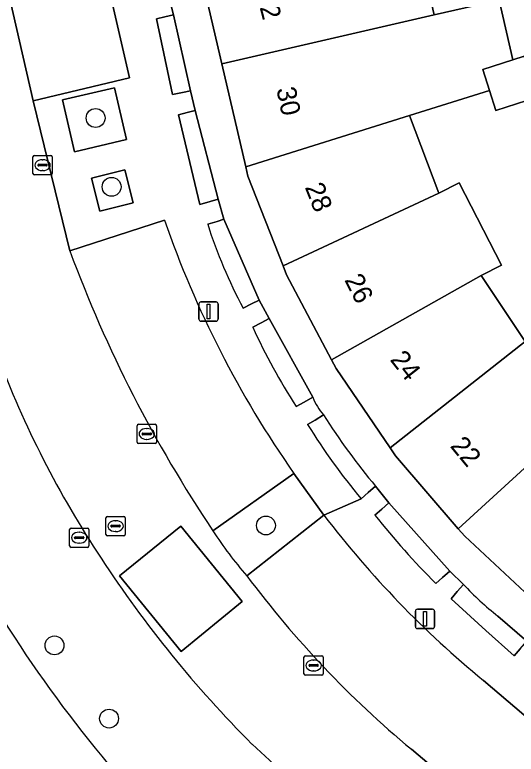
# Model space of a CAD drawing. Extents: x 156412 to 157779, y 382335 to 383768.
# Drawn here: x 157024.9 to 157050.87, y 382894.98 to 382933.25 of the extents above; entities that cross this region are included whole.
import ezdxf

# ---------------------------------------------------------------- set-up
doc = ezdxf.new("R2010")
doc.units = 0
for name, color, linetype in [('IMGEO_Berm_groen', 7, 'Continuous'), ('IMGEO_Boom', 7, 'Continuous'), ('IMGEO_Erf', 7, 'Continuous'), ('IMGEO_Groenvoorziening', 7, 'Continuous'), ('IMGEO_Haag', 7, 'Continuous'), ('IMGEO_Kolk', 7, 'Continuous'), ('IMGEO_Lichtmast', 7, 'Continuous'), ('IMGEO_OVBaan_gesloten', 7, 'Continuous'), ('IMGEO_Pand', 7, 'Continuous'), ('IMGEO_Pand_nummerreeks', 7, 'Continuous'), ('IMGEO_Parkeervlak_open', 7, 'Continuous'), ('IMGEO_Rijbaan_lokaal_gesloten', 7, 'Continuous'), ('IMGEO_Rijbaan_lokaal_open', 7, 'Continuous'), ('IMGEO_Rioolput', 7, 'Continuous'), ('IMGEO_Voetpad_open', 7, 'Continuous')]:
    doc.layers.add(name, color=color, linetype=linetype)

msp = doc.modelspace()

# ---------------------------------------------------------------- linework, layer by layer
at = {"layer": 'IMGEO_Berm_groen'}
for points in [[(157040.904, 382907.361), (157039.349, 382909.517), (157035.16, 382906.543)], [(157036.914, 382904.221), (157040.904, 382907.361)], [(157033.831, 382890.025), (157036.951, 382886.961), (157041.226, 382891.768), (157037.183, 382895.505)]]:
    msp.add_lwpolyline(points, dxfattribs=at)
for centre, radius, start, end in [((157073.619, 382934.389), 53.056, 200.6417, 213.4778), ((157050.99, 382916.677), 18.796, 212.6271, 221.5065), ((157080.152, 382938.419), 60.729, 213.2488, 224.96314), ((157080.911, 382937.438), 66.817, 210.18195, 225.20205), ((157072.354, 382932.861), 64.885, 210.9363, 229.54412)]:
    msp.add_arc(centre, radius, start, end, dxfattribs=at)
at = {"layer": 'IMGEO_Boom'}
for centre in [(157029.082, 382927.908), (157029.912, 382924.346), (157037.906, 382906.82), (157026.953, 382900.613), (157029.779, 382896.825)]:
    msp.add_circle(centre, 0.489, dxfattribs=at)
at = {"layer": 'IMGEO_Erf'}
for points in [[(157033.388, 382968.999), (157025.312, 382967.098), (157026.438, 382961.994), (157026.708, 382960.971), (157027.168, 382959.149), (157027.386, 382958.094), (157028.3, 382954.14), (157028.516, 382953.106), (157029.418, 382949.184), (157029.615, 382948.171), (157030.556, 382944.265), (157030.788, 382943.23), (157031.737, 382939.296), (157031.943, 382938.26), (157032.864, 382934.281), (157033.111, 382933.246), (157034.001, 382929.316), (157034.235, 382928.299), (157035.422, 382923.7), (157035.726, 382922.668), (157037.556, 382918.474), (157038.079, 382917.533), (157040.336, 382913.453)], [(157045.462, 382938.216), (157046.61, 382933.247), (157049.976, 382934.025), (157050.695, 382930.914), (157051.275, 382931.1), (157053.417, 382931.79), (157052.698, 382938.729)], [(157082.934, 382876.466), (157079.046, 382879.765), (157075.157, 382883.065), (157071.268, 382886.365), (157067.379, 382889.664), (157063.49, 382892.964), (157059.602, 382896.263), (157055.713, 382899.563), (157051.839, 382902.879), (157048.2, 382906.264), (157047.866, 382906.651), (157044.615, 382910.42), (157044.337, 382910.83), (157041.542, 382914.944), (157041.305, 382915.392), (157038.976, 382919.795), (157038.795, 382920.253), (157036.968, 382924.901), (157036.857, 382925.379), (157035.623, 382930.709), (157034.472, 382935.677)], [(157051.956, 382928.99), (157049.811, 382928.301), (157049.482, 382929.324), (157045.342, 382928.03), (157046.862, 382924.018), (157047.911, 382924.558), (157050.105, 382920.297), (157049.056, 382919.757), (157051.324, 382916.339)], [(157043.586, 382908.852), (157044.265, 382907.992), (157047.422, 382904.462), (157048.129, 382903.772)], [(157049.923, 382902.132), (157051.414, 382900.824), (157052.174, 382900.111), (157055.262, 382897.527), (157056.106, 382896.836), (157059.141, 382894.249), (157059.952, 382893.555), (157063.086, 382890.937), (157063.917, 382890.211), (157066.966, 382887.621), (157067.779, 382886.911), (157070.828, 382884.357), (157071.619, 382883.687), (157074.699, 382881.06), (157075.52, 382880.404), (157078.608, 382877.784), (157079.414, 382877.065), (157082.481, 382874.48)]]:
    msp.add_lwpolyline(points, dxfattribs=at)
for centre, radius, start, end in [((157042.905, 382914.392), 2.735, 200.0704, 222.6108), ((157069.198, 382930.389), 33.464, 212.2344, 220.0602), ((157058.267, 382913.061), 13.75, 222.4971, 232.6384)]:
    msp.add_arc(centre, radius, start, end, dxfattribs=at)
at = {"layer": 'IMGEO_Groenvoorziening'}
for points in [[(157034.001, 382929.316), (157033.111, 382933.246), (157032.669, 382933.143), (157032.232, 382933.042), (157033.067, 382929.127), (157033.577, 382929.23)], [(157030.679, 382926.79), (157030.054, 382929.478), (157027.363, 382928.852), (157027.988, 382926.164)], [(157035.422, 382923.7), (157034.235, 382928.299), (157033.818, 382928.192), (157033.382, 382928.08), (157034.488, 382923.434), (157035.022, 382923.586)], [(157031.031, 382923.521), (157030.604, 382925.227), (157028.876, 382924.795), (157029.303, 382923.089)]]:
    msp.add_lwpolyline(points, close=True, dxfattribs=at)
for points in [[(157036.723, 382918.071), (157037.163, 382918.284), (157037.556, 382918.474), (157035.726, 382922.668), (157035.374, 382922.558), (157034.891, 382922.406)], [(157039.476, 382912.977), (157039.881, 382913.201), (157040.336, 382913.453), (157038.079, 382917.533), (157037.651, 382917.304), (157037.228, 382917.079)], [(157040.892, 382912.54), (157040.454, 382912.274), (157040.065, 382912.038)], [(157042.838, 382908.2), (157043.203, 382908.518), (157043.586, 382908.852)], [(157046.699, 382903.818), (157047.054, 382904.134), (157047.422, 382904.462), (157044.265, 382907.992), (157043.908, 382907.672), (157043.553, 382907.354)], [(157048.129, 382903.772), (157047.813, 382903.396), (157047.504, 382903.029), (157049.299, 382901.379), (157050.762, 382900.082), (157051.069, 382900.431), (157051.414, 382900.824), (157049.923, 382902.132)]]:
    msp.add_lwpolyline(points, dxfattribs=at)
for centre, radius, start, end in [((157059.514, 382930.257), 25.845, 197.6853, 208.1332), ((157065.241, 382929.764), 30.752, 204.362, 213.0857), ((157069.198, 382930.389), 33.464, 212.2344, 220.0602), ((157068.389, 382929.582), 33.318, 211.7738, 219.9233), ((157075.858, 382932.929), 41.203, 218.3671, 224.9522), ((157058.267, 382913.061), 13.75, 222.4971, 232.6384)]:
    msp.add_arc(centre, radius, start, end, dxfattribs=at)
at = {"layer": 'IMGEO_Haag'}
for points in [[(157034.001, 382929.316), (157033.111, 382933.246), (157032.669, 382933.143), (157032.232, 382933.042), (157033.067, 382929.127), (157033.577, 382929.23)], [(157035.422, 382923.7), (157034.235, 382928.299), (157033.818, 382928.192), (157033.382, 382928.08), (157034.488, 382923.434), (157035.022, 382923.586)]]:
    msp.add_lwpolyline(points, close=True, dxfattribs=at)
for points in [[(157036.723, 382918.071), (157037.163, 382918.284), (157037.556, 382918.474), (157035.726, 382922.668), (157035.374, 382922.558), (157034.891, 382922.406)], [(157039.476, 382912.977), (157039.881, 382913.201), (157040.336, 382913.453), (157038.079, 382917.533), (157037.651, 382917.304), (157037.228, 382917.079)], [(157040.892, 382912.54), (157040.454, 382912.274), (157040.065, 382912.038)], [(157042.838, 382908.2), (157043.203, 382908.518), (157043.586, 382908.852)], [(157046.699, 382903.818), (157047.054, 382904.134), (157047.422, 382904.462), (157044.265, 382907.992), (157043.908, 382907.672), (157043.553, 382907.354)], [(157048.129, 382903.772), (157047.813, 382903.396), (157047.504, 382903.029), (157049.299, 382901.379), (157050.762, 382900.082), (157051.069, 382900.431), (157051.414, 382900.824), (157049.923, 382902.132)]]:
    msp.add_lwpolyline(points, dxfattribs=at)
for centre, radius, start, end in [((157059.514, 382930.257), 25.845, 197.6853, 208.1332), ((157065.241, 382929.764), 30.752, 204.362, 213.0857), ((157069.198, 382930.389), 33.464, 212.2344, 220.0602), ((157068.389, 382929.582), 33.318, 211.7738, 219.9233), ((157075.858, 382932.929), 41.203, 218.3671, 224.9522), ((157058.267, 382913.061), 13.75, 222.4971, 232.6384)]:
    msp.add_arc(centre, radius, start, end, dxfattribs=at)
at = {"layer": 'IMGEO_Kolk'}
for p, q in [((157025.835, 382925.042), (157025.835, 382925.894)), ((157025.91, 382925.968), (157026.762, 382925.968)), ((157026.323, 382925.748), (157026.348, 382925.748)), ((157026.836, 382925.894), (157026.836, 382925.042)), ((157026.094, 382925.462), (157026.094, 382925.474)), ((157026.532, 382925.425), (157026.134, 382925.425)), ((157026.137, 382925.511), (157026.535, 382925.511)), ((157026.578, 382925.474), (157026.578, 382925.462)), ((157026.762, 382924.968), (157025.91, 382924.968)), ((157026.346, 382925.188), (157026.321, 382925.188)), ((157031.232, 382911.131), (157031.232, 382911.983)), ((157031.307, 382912.057), (157032.159, 382912.057)), ((157032.233, 382911.983), (157032.233, 382911.131)), ((157031.491, 382911.551), (157031.491, 382911.563)), ((157031.534, 382911.6), (157031.932, 382911.6)), ((157031.72, 382911.837), (157031.745, 382911.837)), ((157031.975, 382911.563), (157031.975, 382911.551)), ((157031.929, 382911.514), (157031.531, 382911.514)), ((157031.743, 382911.277), (157031.718, 382911.277)), ((157032.159, 382911.057), (157031.307, 382911.057)), ((157039.95, 382900.075), (157040.802, 382900.075)), ((157039.875, 382899.149), (157039.875, 382900.001)), ((157040.363, 382899.855), (157040.388, 382899.855)), ((157040.876, 382900.001), (157040.876, 382899.149)), ((157040.134, 382899.569), (157040.134, 382899.581)), ((157040.572, 382899.532), (157040.174, 382899.532)), ((157040.177, 382899.618), (157040.575, 382899.618)), ((157040.386, 382899.295), (157040.361, 382899.295)), ((157040.618, 382899.581), (157040.618, 382899.569)), ((157040.802, 382899.075), (157039.95, 382899.075))]:
    msp.add_line(p, q, dxfattribs=at)
for points in [[(157025.835, 382925.042), (157025.835, 382925.894)], [(157025.91, 382925.968), (157026.762, 382925.968)], [(157026.836, 382925.894), (157026.836, 382925.042)], [(157026.762, 382924.968), (157025.91, 382924.968)], [(157031.232, 382911.131), (157031.232, 382911.983)], [(157031.307, 382912.057), (157032.159, 382912.057)], [(157032.233, 382911.983), (157032.233, 382911.131)], [(157032.159, 382911.057), (157031.307, 382911.057)], [(157039.95, 382900.075), (157040.802, 382900.075)], [(157039.875, 382899.149), (157039.875, 382900.001)], [(157040.876, 382900.001), (157040.876, 382899.149)], [(157040.802, 382899.075), (157039.95, 382899.075)]]:
    msp.add_lwpolyline(points, dxfattribs=at)
for centre, radius, start, end in [((157025.912, 382925.892), 0.0765, 91.552, 178.448), ((157025.912, 382925.892), 0.0765, 91.552, 178.448), ((157026.76, 382925.892), 0.0765, 1.552, 88.448), ((157026.76, 382925.892), 0.0765, 1.552, 88.448), ((157026.134, 382925.471), 0.0403, 85.8775, 175.7526), ((157026.131, 382925.461), 0.0366, 178.938, 274.7102), ((157026.535, 382925.468), 0.043, 264.8664, 352.4533), ((157026.539, 382925.473), 0.0386, 1.7309, 96.639), ((157025.912, 382925.044), 0.0765, 181.552, 268.448), ((157025.912, 382925.044), 0.0765, 181.552, 268.448), ((157026.76, 382925.044), 0.0765, 271.552, 358.448), ((157026.76, 382925.044), 0.0765, 271.552, 358.448), ((157031.309, 382911.981), 0.0765, 91.552, 178.448), ((157031.309, 382911.981), 0.0765, 91.552, 178.448), ((157032.157, 382911.981), 0.0765, 1.552, 88.448), ((157032.157, 382911.981), 0.0765, 1.552, 88.448), ((157031.531, 382911.56), 0.0403, 85.8775, 175.7526), ((157031.528, 382911.55), 0.0366, 178.938, 274.7102), ((157031.932, 382911.557), 0.043, 264.8664, 352.4533), ((157031.936, 382911.562), 0.0386, 1.7309, 96.639), ((157031.309, 382911.133), 0.0765, 181.552, 268.448), ((157031.309, 382911.133), 0.0765, 181.552, 268.448), ((157032.157, 382911.133), 0.0765, 271.552, 358.448), ((157032.157, 382911.133), 0.0765, 271.552, 358.448), ((157039.952, 382899.999), 0.0765, 91.552, 178.448), ((157039.952, 382899.999), 0.0765, 91.552, 178.448), ((157040.8, 382899.999), 0.0765, 1.552, 88.448), ((157040.8, 382899.999), 0.0765, 1.552, 88.448), ((157040.174, 382899.578), 0.0403, 85.8775, 175.7526), ((157040.171, 382899.568), 0.0366, 178.938, 274.7102), ((157040.575, 382899.575), 0.043, 264.8664, 352.4533), ((157040.579, 382899.58), 0.0386, 1.7309, 96.639), ((157039.952, 382899.151), 0.0765, 181.552, 268.448), ((157039.952, 382899.151), 0.0765, 181.552, 268.448), ((157040.8, 382899.151), 0.0765, 271.552, 358.448), ((157040.8, 382899.151), 0.0765, 271.552, 358.448)]:
    msp.add_arc(centre, radius, start, end, dxfattribs=at)
for centre, major_axis, ratio, start_param, end_param in [((157026.322, 382925.468), (-0.387, 0.002), 0.722429, 4.712389, 7.853982), ((157026.347, 382925.468), (-0.39, 0.002), 0.717154, 1.570796, 4.712389), ((157031.719, 382911.557), (-0.387, 0.002), 0.722429, 4.712389, 7.853982), ((157031.744, 382911.557), (-0.39, 0.002), 0.717154, 1.570796, 4.712389), ((157040.362, 382899.575), (-0.387, 0.002), 0.722429, 4.712389, 7.853982), ((157040.387, 382899.575), (-0.39, 0.002), 0.717154, 1.570796, 4.712389)]:
    msp.add_ellipse(centre, major_axis=major_axis, ratio=ratio, start_param=start_param, end_param=end_param, dxfattribs=at)
at = {"layer": 'IMGEO_Lichtmast'}
for p, q in [((157034.434, 382917.493), (157034.434, 382918.293)), ((157034.434, 382918.293), (157034.434, 382917.493)), ((157034.534, 382918.393), (157035.324, 382918.393)), ((157035.324, 382918.393), (157034.534, 382918.393)), ((157035.424, 382918.293), (157035.424, 382917.493)), ((157035.424, 382917.493), (157035.424, 382918.293)), ((157035.324, 382917.393), (157034.534, 382917.393)), ((157034.534, 382917.393), (157035.324, 382917.393)), ((157045.646, 382901.585), (157045.646, 382902.385)), ((157045.646, 382902.385), (157045.646, 382901.585)), ((157045.746, 382902.485), (157046.536, 382902.485)), ((157046.536, 382902.485), (157045.746, 382902.485)), ((157046.636, 382902.385), (157046.636, 382901.585)), ((157046.636, 382901.585), (157046.636, 382902.385)), ((157046.536, 382901.485), (157045.746, 382901.485)), ((157045.746, 382901.485), (157046.536, 382901.485))]:
    msp.add_line(p, q, dxfattribs=at)
for points in [[(157034.854, 382918.268), (157035.004, 382918.268), (157035.004, 382917.518), (157034.854, 382917.518), (157034.854, 382918.268)], [(157046.066, 382902.36), (157046.216, 382902.36), (157046.216, 382901.61), (157046.066, 382901.61), (157046.066, 382902.36)]]:
    msp.add_lwpolyline(points, dxfattribs=at)
for centre, start, end in [((157034.534, 382918.293), 90, 180), ((157034.534, 382918.293), 90, 180), ((157035.324, 382918.293), 0, 90), ((157035.324, 382918.293), 360, 90), ((157034.534, 382917.493), 180, 270), ((157034.534, 382917.493), 180, 270), ((157035.324, 382917.493), 270, 0), ((157035.324, 382917.493), 270, 0), ((157045.746, 382902.385), 90, 180), ((157045.746, 382902.385), 90, 180), ((157046.536, 382902.385), 0, 90), ((157046.536, 382902.385), 360, 90), ((157045.746, 382901.585), 180, 270), ((157045.746, 382901.585), 180, 270), ((157046.536, 382901.585), 270, 0), ((157046.536, 382901.585), 270, 0)]:
    msp.add_arc(centre, 0.1, start, end, dxfattribs=at)
at = {"layer": 'IMGEO_OVBaan_gesloten'}
for centre, radius, start, end in [((157080.911, 382937.438), 66.817, 210.18195, 225.20205), ((157072.354, 382932.861), 64.885, 210.9363, 229.54412)]:
    msp.add_arc(centre, radius, start, end, dxfattribs=at)
at = {"layer": 'IMGEO_Pand'}
for points in [[(157046.61, 382933.247), (157045.462, 382938.216), (157034.472, 382935.677), (157035.623, 382930.709)], [(157049.482, 382929.324), (157049.133, 382930.411), (157050.695, 382930.914), (157049.976, 382934.025), (157046.61, 382933.247), (157035.623, 382930.709), (157036.857, 382925.379), (157045.342, 382928.03)], [(157051.275, 382931.1), (157050.695, 382930.914), (157049.133, 382930.411), (157049.482, 382929.324), (157049.811, 382928.301), (157051.956, 382928.99)], [(157046.862, 382924.018), (157045.342, 382928.03), (157036.857, 382925.379), (157036.968, 382924.901), (157038.795, 382920.253)], [(157046.862, 382924.018), (157038.795, 382920.253), (157038.976, 382919.795), (157041.305, 382915.392), (157049.056, 382919.757), (157050.105, 382920.297), (157047.911, 382924.558)], [(157041.305, 382915.392), (157041.542, 382914.944), (157044.337, 382910.83), (157051.324, 382916.339), (157049.056, 382919.757)], [(157055.327, 382913.457), (157056.229, 382914.217), (157053.225, 382917.778), (157051.324, 382916.339), (157044.337, 382910.83), (157044.615, 382910.42), (157047.866, 382906.651)], [(157051.839, 382902.879), (157058.192, 382910.708), (157055.327, 382913.457), (157047.866, 382906.651), (157048.2, 382906.264)]]:
    msp.add_lwpolyline(points, close=True, dxfattribs=at)
at = {"layer": 'IMGEO_Parkeervlak_open'}
msp.add_lwpolyline([(157027.462, 382944.644), (157022.489, 382943.43), (157025.841, 382928.792), (157030.834, 382929.979)], close=True, dxfattribs=at)
for points in [[(157032.645, 382922.627), (157027.746, 382921.036)], [(157035.16, 382906.543), (157039.349, 382909.517)], [(157040.904, 382907.361), (157036.914, 382904.221)], [(157045.439, 382895.241), (157050.124, 382891.278), (157053.358, 382895.243), (157049.173, 382898.793)]]:
    msp.add_lwpolyline(points, dxfattribs=at)
for centre, radius, start, end in [((157083.182, 382940.201), 53.505, 199.1746, 214.9927), ((157092.439, 382944.987), 68.984, 200.31605, 213.86864), ((157082.134, 382938.878), 51.896, 217.395, 230.5703), ((157079.013, 382935.651), 52.538, 216.7436, 230.2785)]:
    msp.add_arc(centre, radius, start, end, dxfattribs=at)
at = {"layer": 'IMGEO_Rijbaan_lokaal_gesloten'}
for points in [[(157027.746, 382921.036), (157025.841, 382928.792), (157022.489, 382943.43), (157021.849, 382946.226), (157017.881, 382963.432)], [(157037.183, 382895.505), (157041.226, 382891.768), (157042.249, 382890.822), (157044.62, 382888.63), (157061.218, 382874.44), (157077.707, 382860.082), (157081.107, 382857.364), (157084.265, 382862.356), (157082.72, 382863.641), (157081.081, 382865.071), (157069.573, 382874.83), (157067.367, 382876.712), (157055.811, 382886.492), (157050.124, 382891.278), (157045.439, 382895.241)]]:
    msp.add_lwpolyline(points, dxfattribs=at)
msp.add_lwpolyline([(157033.491, 382906.788), (157036.681, 382902.879), (157033.518, 382900.298), (157030.328, 382904.207)], close=True, dxfattribs=at)
for centre, radius, start, end in [((157092.439, 382944.987), 68.984, 200.31605, 213.86864), ((157073.619, 382934.389), 53.056, 200.6417, 213.4778), ((157050.99, 382916.677), 18.796, 212.6271, 221.5065), ((157080.152, 382938.419), 60.729, 213.2488, 224.96314), ((157079.013, 382935.651), 52.538, 216.7436, 230.2785)]:
    msp.add_arc(centre, radius, start, end, dxfattribs=at)
at = {"layer": 'IMGEO_Rijbaan_lokaal_open'}
msp.add_lwpolyline([(157033.518, 382900.298), (157036.681, 382902.879), (157033.491, 382906.788), (157030.328, 382904.207)], close=True, dxfattribs=at)
at = {"layer": 'IMGEO_Rioolput'}
for p, q in [((157029.618, 382906.361), (157029.618, 382907.213)), ((157029.693, 382907.287), (157030.545, 382907.287)), ((157030.106, 382907.067), (157030.131, 382907.067)), ((157030.619, 382907.213), (157030.619, 382906.361)), ((157027.735, 382905.762), (157027.735, 382906.614)), ((157027.81, 382906.688), (157028.662, 382906.688)), ((157028.736, 382906.614), (157028.736, 382905.762)), ((157029.877, 382906.781), (157029.877, 382906.793)), ((157030.315, 382906.744), (157029.917, 382906.744)), ((157029.92, 382906.83), (157030.318, 382906.83)), ((157030.361, 382906.793), (157030.361, 382906.781)), ((157027.994, 382906.182), (157027.994, 382906.194)), ((157028.037, 382906.231), (157028.435, 382906.231)), ((157028.223, 382906.468), (157028.248, 382906.468)), ((157028.478, 382906.194), (157028.478, 382906.182)), ((157030.545, 382906.287), (157029.693, 382906.287)), ((157030.129, 382906.507), (157030.104, 382906.507)), ((157028.432, 382906.145), (157028.034, 382906.145)), ((157028.246, 382905.908), (157028.221, 382905.908)), ((157028.662, 382905.688), (157027.81, 382905.688))]:
    msp.add_line(p, q, dxfattribs=at)
for points in [[(157029.618, 382906.361), (157029.618, 382907.213)], [(157029.693, 382907.287), (157030.545, 382907.287)], [(157030.619, 382907.213), (157030.619, 382906.361)], [(157027.735, 382905.762), (157027.735, 382906.614)], [(157027.81, 382906.688), (157028.662, 382906.688)], [(157028.736, 382906.614), (157028.736, 382905.762)], [(157030.545, 382906.287), (157029.693, 382906.287)], [(157028.662, 382905.688), (157027.81, 382905.688)]]:
    msp.add_lwpolyline(points, dxfattribs=at)
for centre, radius, start, end in [((157029.695, 382907.211), 0.0765, 91.552, 178.448), ((157029.695, 382907.211), 0.0765, 91.552, 178.448), ((157030.543, 382907.211), 0.0765, 1.552, 88.448), ((157030.543, 382907.211), 0.0765, 1.552, 88.448), ((157027.812, 382906.612), 0.0765, 91.552, 178.448), ((157027.812, 382906.612), 0.0765, 91.552, 178.448), ((157028.66, 382906.612), 0.0765, 1.552, 88.448), ((157028.66, 382906.612), 0.0765, 1.552, 88.448), ((157029.917, 382906.79), 0.0403, 85.8775, 175.7526), ((157029.914, 382906.78), 0.0366, 178.938, 274.7102), ((157030.318, 382906.787), 0.043, 264.8664, 352.4533), ((157030.322, 382906.792), 0.0386, 1.7309, 96.639), ((157028.034, 382906.191), 0.0403, 85.8775, 175.7526), ((157028.031, 382906.181), 0.0366, 178.938, 274.7102), ((157028.435, 382906.188), 0.043, 264.8664, 352.4533), ((157028.439, 382906.193), 0.0386, 1.7309, 96.639), ((157029.695, 382906.363), 0.0765, 181.552, 268.448), ((157029.695, 382906.363), 0.0765, 181.552, 268.448), ((157030.543, 382906.363), 0.0765, 271.552, 358.448), ((157030.543, 382906.363), 0.0765, 271.552, 358.448), ((157027.812, 382905.764), 0.0765, 181.552, 268.448), ((157027.812, 382905.764), 0.0765, 181.552, 268.448), ((157028.66, 382905.764), 0.0765, 271.552, 358.448), ((157028.66, 382905.764), 0.0765, 271.552, 358.448)]:
    msp.add_arc(centre, radius, start, end, dxfattribs=at)
for centre, major_axis, ratio, start_param, end_param in [((157030.105, 382906.787), (-0.387, 0.002), 0.722429, 4.712389, 7.853982), ((157030.13, 382906.787), (-0.39, 0.002), 0.717154, 1.570796, 4.712389), ((157028.222, 382906.188), (-0.387, 0.002), 0.722429, 4.712389, 7.853982), ((157028.247, 382906.188), (-0.39, 0.002), 0.717154, 1.570796, 4.712389)]:
    msp.add_ellipse(centre, major_axis=major_axis, ratio=ratio, start_param=start_param, end_param=end_param, dxfattribs=at)
at = {"layer": 'IMGEO_Voetpad_open'}
for points in [[(157026.438, 382961.994), (157025.955, 382961.882), (157025.511, 382961.78), (157024.116, 382967.788), (157022.174, 382967.245), (157022.818, 382964.629), (157026.752, 382947.531), (157027.462, 382944.644), (157030.834, 382929.979), (157025.841, 382928.792), (157027.746, 382921.036), (157032.645, 382922.627)], [(157034.891, 382922.406), (157035.374, 382922.558), (157035.726, 382922.668), (157035.422, 382923.7), (157035.022, 382923.586), (157034.488, 382923.434), (157033.382, 382928.08), (157033.818, 382928.192), (157034.235, 382928.299), (157034.001, 382929.316), (157033.577, 382929.23), (157033.067, 382929.127), (157032.232, 382933.042), (157032.669, 382933.143), (157033.111, 382933.246), (157032.864, 382934.281)], [(157037.228, 382917.079), (157037.651, 382917.304), (157038.079, 382917.533), (157037.556, 382918.474), (157037.163, 382918.284), (157036.723, 382918.071)], [(157040.336, 382913.453), (157039.881, 382913.201), (157039.476, 382912.977)], [(157040.065, 382912.038), (157040.454, 382912.274), (157040.892, 382912.54)], [(157039.349, 382909.517), (157040.904, 382907.361), (157042.838, 382908.2)], [(157043.553, 382907.354), (157043.908, 382907.672), (157044.265, 382907.992), (157043.586, 382908.852), (157043.203, 382908.518), (157042.838, 382908.2), (157040.904, 382907.361)], [(157051.069, 382900.431), (157050.762, 382900.082), (157049.299, 382901.379), (157047.504, 382903.029), (157047.813, 382903.396), (157048.129, 382903.772), (157047.422, 382904.462), (157047.054, 382904.134), (157046.699, 382903.818)], [(157049.173, 382898.793), (157053.358, 382895.243), (157050.124, 382891.278), (157055.811, 382886.492), (157059.08, 382890.358), (157070.666, 382880.6), (157072.863, 382878.7), (157084.374, 382868.962), (157085.226, 382868.226)]]:
    msp.add_lwpolyline(points, dxfattribs=at)
for points in [[(157030.054, 382929.478), (157030.679, 382926.79), (157027.988, 382926.164), (157027.363, 382928.852)], [(157031.031, 382923.521), (157029.303, 382923.089), (157028.876, 382924.795), (157030.604, 382925.227)]]:
    msp.add_lwpolyline(points, close=True, dxfattribs=at)
for centre, radius, start, end in [((157083.182, 382940.201), 53.505, 199.1746, 214.9927), ((157059.514, 382930.257), 25.845, 197.6853, 208.1332), ((157065.241, 382929.764), 30.752, 204.362, 213.0857), ((157042.905, 382914.392), 2.735, 200.0704, 222.6108), ((157068.389, 382929.582), 33.318, 211.7738, 219.9233), ((157082.134, 382938.878), 51.896, 217.395, 230.5703), ((157075.858, 382932.929), 41.203, 218.3671, 224.9522)]:
    msp.add_arc(centre, radius, start, end, dxfattribs=at)

# ---------------------------------------------------------------- texts
at = {"layer": 'IMGEO_Pand_nummerreeks'}
for s, rotation, p in [('32', 284.7393, (157037.383, 382934.362)), ('30', 281.8829, (157038.441, 382929.413)), ('28', 291.5351, (157039.907, 382924.334)), ('26', 297.2091, (157041.948, 382919.532)), ('24', 307.9904, (157044.297, 382915.391)), ('22', 309.6357, (157047.408, 382910.917))]:
    msp.add_text(s, height=1, rotation=rotation, dxfattribs=at).set_placement(p)

doc.saveas('drawing.dxf')
